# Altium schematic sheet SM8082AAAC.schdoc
size 127 x 101 mm
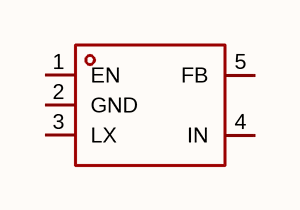
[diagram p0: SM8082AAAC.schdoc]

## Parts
U?  sm8082aaac  [SOT-23-5_L3.0-W1.7-P0.95-LS2.8-BL]  (value not drawn)

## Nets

Not connected (* = marked no-connect by the designer): U? 1(EN) 2(GND) 3(LX) 4(IN) 5(FB)

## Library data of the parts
U? = sm8082aaac: 功能类型:降压型;工作电压:2.5V~5.5V;输出电压:-;输出电流:2A;输出类型:可调;; Manufacturer: Silergy(矽力杰); AddInBom: yes; ModelId: 0a2a1b8f50944f73965918ad6e5fe167; ModelName: SOT-23-5_L2.9-W1.6-H1.1-LS2.8-P0.95; ModelTransform: 118.60433,114.173,0,90,0,0,0.0005,0.0005,0; Function: 降压型; Output Current: 2A; Frequency - Switching: 1.5MHz; Synchronous Rectifier: 是; Number of Outputs: 1; Topology: 降压式; Quiescent Current: 70uA; Switch tube (built-in/external): 内置; Output Type: 可调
